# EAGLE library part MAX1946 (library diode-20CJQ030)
Maxim's MAX1946 Single USB Switch with Autoreset and Fault Blanking in Tiny QFN Description: The MAX1946 single current-limited switch with autoreset supplies a guaranteed 500mA load in accordance with USB specifications. The MAX1946 operates from a 2.7V to 5.5V input supply and consumes only 40µA of quiescent current when operating and only 3µA in shutdown. Selectable active-high/active-low control logic and shutdown control provide additional flexibility. An autoreset feature latches the switch off in the event of a short circuit, saving system power. The switch reactivates upon removal of the shorted condition. The MAX1946 provides several safety features to protect the USB port. Built-in thermal-overload protection turns off the switch when the die temperature exceeds +160°C. Accurate internal current-limiting circuitry protects the input supply against both overload and shortcircuit conditions. An open-drain fault signal, (FAULT), notifies the microprocessor (µP) when a thermal overload, current-limit, undervoltage lockout (UVLO), or short-circuit fault occurs. A 20ms fault-blanking feature enables the circuit to ignore momentary faults, such as those caused when hot-swapping a capacitive load, preventing false alarms to the host system. The faultblanking feature prevents fault signals from being issued when the device powers up the load. The MAX1946 is available in a space-saving 8-pin thin QFN package and operates over the extended (-40°C to +85°C) temperature range.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
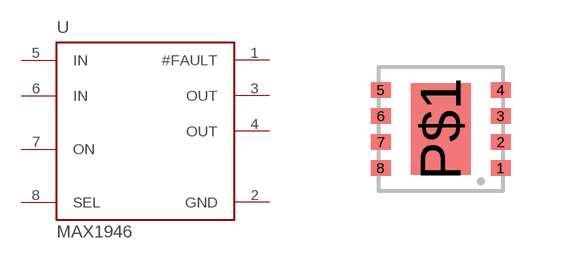
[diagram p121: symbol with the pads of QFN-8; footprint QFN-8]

Designator prefix U

## MAX1946-ETA  [QFN-8]
1  #FAULT  out
2  GND  pwr
3  OUT  out
4  OUT  out
5  IN  in
6  IN  in
7  ON  in
8  SEL  in

## Footprint QFN-8 (pad centres in mm)
smd 0.5 x 0.38: 1 1.5,-0.975; 2 1.5,-0.325; 3 1.5,0.325; 4 1.5,0.975; 5 -1.5,0.975; 6 -1.5,0.325; 7 -1.5,-0.325; 8 -1.5,-0.975
smd 1.5 x 2.3: P$1 0,0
